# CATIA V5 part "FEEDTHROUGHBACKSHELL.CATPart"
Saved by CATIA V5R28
Part number: FEEDTHROUGHBACKSHELL
Revision: --B
Publications: "Logical Termination.1", "BCP", "BaCP", "MasterKeywayAxis", "Face_generated(BaCP).2", "Axis_generated(BaCP).1", "Face_generated(BaCP).3", "BCPRPoint_generated(BCP).1", "BCPPlane_generated(BCP).1", "CAV", "Face_generated(CAV)", "Axis_generated(CAV)"
Bounding box of the stored display mesh (mm): x 0 to 58.547, y -21.178 to 21.178, z -21.194 to 21.194
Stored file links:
  C:\Users\ajc8720\Documents\BOEING_WORK\0001-2CES\004-AP242\Boeing-Generic_Harness_R3\FEEDTHROUGHBACKSHELL.CATPart
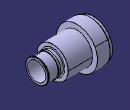
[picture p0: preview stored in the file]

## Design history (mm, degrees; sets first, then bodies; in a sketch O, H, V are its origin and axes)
Parameters
  PartNumber = "FEEDTHROUGHBACKSHELL"
AxisSystem1 "MasterKeywayAxis": origin (0, 0, 0), X (1, 0, 0), Y (0, 1, 0), Z (0, 0, 1)
Set1
  Point1: (41.91 {= Sketch2.distance(P3 V)}, 12.7, 0)
  Plane1: type 1Line1Pt, RefPoint Point1, Line Sketch2.L1
  Point2: type OnCurve, Support Sketch2.L4, Ratio 0.5
  Line1: type PtDir, RefPoint Point2, Direction (0, 1, 0), Start 0, End 5.08
  Point3: type OnCurve, Support Line1, Ratio 0.5
  Plane2: type 1Line1Pt, RefPoint Point3, Line Sketch2.L4
  Point4: type Center, Curve edge [face of Shaft1 from Sketch1.L5 | face of Shaft1 from Sketch1.L6]
  Plane3: type Tangent, Support face of Shaft1 from Sketch1.L5, RefPoint Point4
  Plane4: type OffsetPt, RefPlane Plane2, RefPoint Sketch2.P10
Set2 "EGF"
  Set3 "BCP"
    Point5 "BCPRPoint": type Center, Curve edge [face of Shaft2 from Sketch5.L6 | face of Shaft2 from Sketch5.L5]
    Plane5 "BCPPlane": type Tangent, Support face of Shaft2 from Sketch5.L6, RefPoint Point5
  Set4 "BaCP"
    Point6 "BaCPRPoint": type Center, Curve edge [face of Shaft1 from Sketch1.L6 | face of Shaft1 from Sketch1.L7]
    Plane6 "BaCPCPlane": type Tangent, Support face of Shaft1 from Sketch1.L7, RefPoint Point6
    Line2 "BaCPOLine": type PtDir, RefPoint Point6, Direction zx-plane, Start 0, End 12.7
  Set5 "CAV"
    Point7 "CAVRPoint": type Center, Curve edge [start face of Pad2 | face of Shaft2 from Sketch5.L8]
    Plane7 "CAVCPlane": type Tangent, Support face of Shaft2 from Sketch5.L6, RefPoint Point7
    Line3 "CAVOLine": type PtDir, RefPoint Point7, Direction zx-plane, Start 0, End 12.7
Body1 (main body)
  Sketch1 on xy-plane, origin (0, 0, 0), H (1, 0, 0), V (0, 1, 0)
    line L1 (0, 17.399) -> (0, 19.939)
    line L2 (0, 19.939) -> (2.286, 19.939)
    point P3 (2.286, 19.939)
    line L3 (2.286, 19.939) -> (3.556, 21.209)
    line L4 (3.556, 21.209) -> (16.764, 21.209)
    line L5 (16.764, 21.209) -> (16.764, 12.6365)
    line L6 (16.764, 12.6365) -> (7.747, 12.6365)
    line L7 (7.747, 12.6365) -> (7.747, 17.399)
    line L8 (7.747, 17.399) -> (0, 17.399)
    axis line L9 (-2.2417, 0) -> (20.7737, 0)
    point P9 (-2.2417, 0)
    distance P3 L1 = 2.286
    angle L3 L4 = 45
    distance L1 L7 = 7.747
    distance L1 L5 = 16.764
    distance L6 H = 12.6365
    distance L8 H = 17.399
    distance L2 H = 19.939
    distance L4 H = 21.209
    vertical: L1 V, L5 V, L7 V
    horizontal: L2 H, L4 H, L6 H, L8 H, L9 H
    coincidence: L1 V, P9 H
  Shaft1: profile Sketch1, axis Sketch1.L9, angle 360
  Sketch2 on zx-plane, origin (0, 0, 0), H (-1, 0, 0), V (0, 0, 1)
    line L1 (-41.91, 0) -> (-41.91, 8.947)
    line L2 (-41.91, 0) -> (-36.5055, 0)
    point P3 (-41.91, 0)
    line L3 (-41.91, 0) -> (-42.037, 0)
    line L4 (-42.037, 0) -> (-42.037, -14.6085)
    reference projected point E1 (-41.91, 0) from Point1
    point P7 (-42.037, 0)
    line L5 (-48.387, 0) -> (-48.387, -14.6085)
    construction line L6 (-42.037, 0) -> (-48.387, 0)
    construction line L7 (-42.037, -14.6085) -> (-48.387, -14.6085)
    point P10 (-48.387, 0)
    point P11 (-41.91, 0)
    angle L1 V = 0
    distance P3 V = 41.91
    distance L4 E1 = 0.127
    angle L3 H = 0
    distance L4 L5 = 6.35
    horizontal: L2 H
    coincidence: L2 P3, L1 P3, L2 H, L4 P7, L3 P7, L3 P10, L5 P10, L1 P11, L3 P11
    perpendicularity: L4 L3, L6 L4, L6 L5, L7 L4, L7 L5
  Sketch3 on Plane3, origin (16.764, 0, 0), H (0, -1, 0), V (0, 0, 1)
    circle A1 centre (0, 0) radius 12.6365
    circle A2 centre (0, 0) radius 16.0655
    radius A1 = 12.6365
    radius A2 = 16.0655
  Pad1: profile Sketch3, direction (1, 0, 0), up to Plane1
  Sketch4 on Plane2, origin (42.037, 0, -156.1191), H (0, 1, 0), V (0, 0, 1)
    circle A1 centre (0, 156.1191) radius 9.525
    point P1 (0, 156.1191)
    circle A2 centre (0, 156.1191) radius 16.0655
    reference projected point E1 (0, 156.1191) from Sketch2.P7
    radius A1 = 9.525
    radius A2 = 16.0655
    coincidence: P1 V, P1 E1
  Pad2: profile Sketch4, direction (-1, 0, 0), up to Plane1
  Sketch5 on zx-plane, origin (0, 0, 0), H (-1, 0, 0), V (0, 0, 1)
    construction line L1 (-24.3125, 0) -> (-41.91, 0)
    point P1 (-24.3125, 0)
    point P2 (-41.91, 0)
    construction line L2 (-41.91, 0) -> (-42.037, 0)
    point P3 (-42.037, 0)
    construction line L3 (-42.037, 0) -> (-42.037, 10.6975)
    point P5 (-58.547, 11.8999)
    point P6 (-42.037, 11.1125)
    line L4 (-42.037, 11.1125) -> (-42.037, 9.525)
    line L5 (-42.037, 9.525) -> (-58.547, 9.525)
    line L6 (-58.547, 9.525) -> (-58.547, 11.3919)
    axis line L7 (-42.037, 0) -> (-72.0737, 0)
    line L8 (-42.037, 11.1125) -> (-45.466, 11.1125)
    line L9 (-57.023, 11.1125) -> (-57.023, 11.3919)
    point P11 (-57.023, 9.525)
    point P12 (-57.023, 11.8999)
    construction line L10 (-58.547, 9.525) -> (-57.023, 9.525)
    construction line L11 (-58.547, 11.8999) -> (-57.023, 11.8999)
    line L12 (-47.371, 11.1125) -> (-47.371, 11.8999)
    point P13 (-47.371, 9.525)
    point P14 (-47.371, 11.8999)
    construction line L13 (-57.023, 9.525) -> (-47.371, 9.525)
    construction line L14 (-57.023, 11.8999) -> (-47.371, 11.8999)
    line L15 (-45.466, 11.1125) -> (-45.466, 11.8999)
    point P15 (-45.466, 9.525)
    point P16 (-45.466, 11.8999)
    construction line L16 (-47.371, 9.525) -> (-45.466, 9.525)
    construction line L17 (-47.371, 11.8999) -> (-45.466, 11.8999)
    line L18 (-45.466, 11.8999) -> (-47.371, 11.8999)
    point P17 (-47.371, 11.1125)
    line L19 (-47.371, 11.1125) -> (-57.023, 11.1125)
    point P22 (-47.371, 11.8999)
    line L20 (-57.531, 11.8999) -> (-58.039, 11.8999)
    arc A1 centre (-57.531, 11.3919) radius 0.508 from (-57.023, 11.3919) to (-57.531, 11.8999) ccw
    arc A2 centre (-58.039, 11.3919) radius 0.508 from (-58.547, 11.3919) to (-58.039, 11.8999) cw
    distance P2 V = 41.91
    angle L1 L2 = 0
    distance P2 P3 = 0.127
    distance P6 L2 = 11.1125
    distance L4 L6 = 16.51
    distance L5 L2 = 9.525
    distance L6 L9 = 1.524
    distance L9 L12 = 9.652
    distance L12 L15 = 1.905
    distance L18 L7 = 11.8999
    radius A1 = 0.508
    radius A2 = 0.508
    coincidence: P1 H, L4 L3, L8 P6, P16 L15, P14 L12, L8 L19, L12 P17, P17 L19, P13 L12, P11 L9, P17 L8, P15 L15, P5 L18, L18 L20, L12 P22, P12 L20, P5 L6, P22 L20, P12 L9, P22 L18
    horizontal: L1 H
    perpendicularity: L3 L2, L10 L6, L10 L9, L11 L6, L11 L9, L13 L9, L13 L12, L14 L9, L14 L12, L16 L12, L16 L15, L17 L12, L17 L15, L19 L9
    parallelism: L7 L2, L18 L2
    tangency: A1 L9, A1 L20, A2 L6, A2 L20
  Shaft2: profile Sketch5, axis Sketch5.L7, angle 360
Body2 "BaCP"
  Sketch6 "Sketch" on Plane6, origin (7.747, 0, 0), H (0, 1, 0), V (0, 0, 1)
    line L1 (-0.672, 0.762) -> (0.672, 0.762)
    point P1 (-0.672, 0.762)
    point P2 (0.672, 0.762)
    arc A1 centre (0, 0) radius 1.016 from (-1.016, 0) to (1.016, 0) ccw
    point P3 (0, 0)
    point P4 (-1.016, 0)
    point P5 (1.016, 0)
    reference projected point E1 (0, 0) from Point6
    arc A2 centre (0, 0) radius 1.016 from (1.016, 0) to (0.672, 0.762) ccw
    point P6 (0, 0)
    point P7 (1.016, 0)
    point P8 (0.672, 0.762)
    arc A3 centre (0, 0) radius 1.016 from (-0.672, 0.762) to (-1.016, 0) ccw
    point P9 (0, 0)
    point P10 (-0.672, 0.762)
    point P11 (-1.016, 0)
    reference projected point E2 (0, 0) from Point6
    reference projected point E3 (0, 0) from Point6
    length L1 = 1.344
    radius A1 = 1.016
    radius A3 = 1.016
    radius A2 = 1.016
    distance L1 P5 = 0.762
    distance P4 L1 = 0.762
    distance P7 L1 = 0.762
    distance P11 L1 = 0.762
    coincidence: P3 E1, P6 E2, P9 E3, P8 P2, P10 P1
    horizontal: L1 H
  Pad3: profile Sketch6, direction (1, 0, 0), length 0.508, opposite side up to Plane6
Body3 "CAV"
  Sketch7 "Copy of Sketch.1" on Plane7, origin (42.037, 0, 0), H (0, 1, 0), V (0, 0, 1)
    circle A1 centre (0, 0) radius 1.27
    point P1 (0, 0)
    reference projected point E1 (0, 0) from Point7
    radius A1 = 1.27
    coincidence: P1 E1
  Pad4: profile Sketch7, direction (1, 0, 0), length 0.254, opposite side length 0.254
  Sketch8 "Copy of Sketch.2" on Plane7, origin (42.037, 0, 0), H (0, 1, 0), V (0, 0, 1)
    line L1 (-0.672, 0.762) -> (0.672, 0.762)
    point P1 (-0.672, 0.762)
    point P2 (0.672, 0.762)
    arc A1 centre (0, 0) radius 1.016 from (-1.016, 0) to (1.016, 0) ccw
    point P3 (0, 0)
    point P4 (-1.016, 0)
    point P5 (1.016, 0)
    reference projected point E1 (0, 0) from Point7
    arc A2 centre (0, 0) radius 1.016 from (1.016, 0) to (0.672, 0.762) ccw
    point P6 (0, 0)
    point P7 (1.016, 0)
    point P8 (0.672, 0.762)
    arc A3 centre (0, 0) radius 1.016 from (-0.672, 0.762) to (-1.016, 0) ccw
    point P9 (0, 0)
    point P10 (-0.672, 0.762)
    point P11 (-1.016, 0)
    reference projected point E2 (0, 0) from Point7
    reference projected point E3 (0, 0) from Point7
    length L1 = 1.344
    radius A1 = 1.016
    radius A3 = 1.016
    radius A2 = 1.016
    distance L1 P5 = 0.762
    distance P4 L1 = 0.762
    distance P7 L1 = 0.762
    distance P11 L1 = 0.762
    coincidence: P3 E1, P6 E2, P9 E3, P8 P2, P10 P1
    horizontal: L1 H
  Pocket1: profile Sketch8, direction (1, 0, 0), through (limit type 6)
